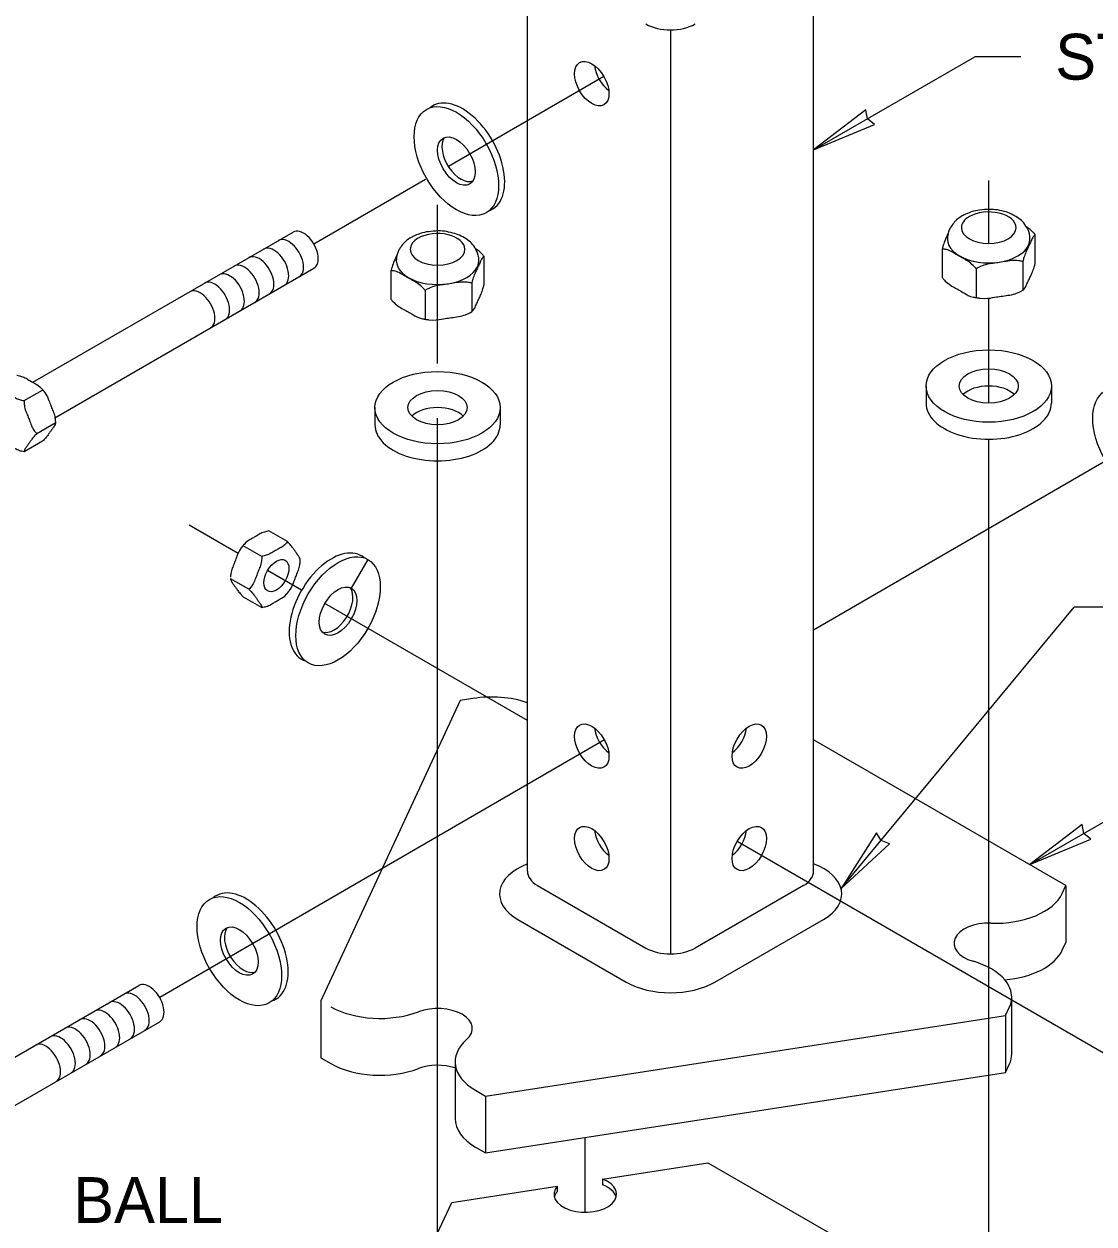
# Model space of a CAD drawing. Extents: x 99862 to 103151, y 99997 to 117076.
# Drawn here: x 100962.7 to 101336, y 103787.3 to 104205.8 of the extents above; entities that cross this region are included whole.
import ezdxf

# ---------------------------------------------------------------- set-up
doc = ezdxf.new("R2010")
doc.units = 0
for name, color, linetype in [('Level 12', 7, 'Continuous'), ('Level 13', 7, 'Continuous'), ('Level 15', 7, 'Continuous'), ('Level 20', 7, 'Continuous'), ('Level 4', 7, 'Continuous'), ('Level 6', 7, 'Continuous'), ('Level 7', 7, 'Continuous'), ('Level 8', 7, 'Continuous')]:
    doc.layers.add(name, color=color, linetype=linetype)

msp = doc.modelspace()

# ---------------------------------------------------------------- linework, layer by layer
at = {"layer": 'Level 12'}
for p, q in [((101315.52, 104122.4), (101315.52, 104132.32)), ((101283.03, 104127.29), (101283.03, 104117.38)), ((101123.26, 104114.87), (101123.26, 104124.78)), ((101311.17, 104122.94), (101311.17, 104113.02)), ((101090.76, 104119.76), (101090.76, 104109.84)), ((101294.92, 104120.42), (101294.92, 104110.51)), ((101118.91, 104115.4), (101118.91, 104105.49)), ((101102.66, 104112.89), (101102.66, 104102.98)), ((101277.42, 104079.54), (101277.42, 104073.59)), ((101321.13, 104079.54), (101321.13, 104073.59)), ((101085.16, 104072.01), (101085.16, 104066.06)), ((101128.86, 104072.01), (101128.86, 104066.06))]:
    msp.add_line(p, q, dxfattribs=at)
for centre, major_axis, start_param, end_param in [((101299.28, 104134.76), (9.54, 0), 2.356194, 3.141593), ((101299.28, 104134.76), (9.54, 0), 6.283185, 8.63938), ((101299.28, 104134.76), (9.54, 0), 3.141593, 6.283185), ((101107.01, 104127.23), (9.54, 0), 2.356194, 3.141593), ((101107.01, 104127.23), (9.54, 0), 6.283185, 8.63938), ((101299.28, 104130.79), (-14.39, 0), 0, 3.141593), ((101107.01, 104127.23), (9.54, 0), 3.141593, 6.283185), ((101107.01, 104123.26), (-14.39, 0), 0, 3.141593), ((101299.28, 104073.59), (-10.32, 0), 3.664192, 5.760586), ((101107.01, 104066.06), (-10.32, 0), 3.664192, 5.760586), ((101299.28, 104073.59), (-21.85, 0), 0, 3.141593), ((101107.01, 104066.06), (-21.85, 0), 0, 3.141593)]:
    msp.add_ellipse(centre, major_axis=major_axis, ratio=0.57735, start_param=start_param, end_param=end_param, dxfattribs=at)
for centre, major_axis in [((101299.28, 104079.54), (-21.85, 0)), ((101107.01, 104072.01), (-21.85, 0)), ((101299.28, 104079.54), (-10.32, 0)), ((101107.01, 104072.01), (-10.32, 0))]:
    msp.add_ellipse(centre, major_axis=major_axis, ratio=0.57735, dxfattribs=at)
for points, degree in [([(101313.67, 104130.79), (101313.67, 104132.32), (101313.12, 104134.07), (101311.44, 104136.67), (101310.04, 104137.95), (101307.35, 104139.55), (101305.62, 104140.23), (101302.17, 104141.06), (101299.79, 104141.24), (101295.8, 104140.97), (101293.5, 104140.45), (101291.22, 104139.49), (101290.6, 104139.18), (101288.76, 104138.12), (101287.39, 104136.94), (101286.01, 104135.02), (101285.52, 104134.08), (101285.03, 104132.5), (101284.88, 104131.57), (101284.88, 104130.79)], 3), ([(101315.52, 104132.32), (101315.27, 104132.66), (101314.96, 104132.99), (101314.03, 104133.9), (101313.29, 104134.46), (101312.54, 104134.96)], 3), ([(101121.4, 104123.26), (101121.4, 104124.79), (101120.85, 104126.54), (101119.18, 104129.14), (101117.77, 104130.41), (101115.08, 104132.02), (101113.35, 104132.7), (101109.9, 104133.52), (101107.53, 104133.71), (101103.53, 104133.43), (101101.23, 104132.91), (101098.95, 104131.95), (101098.33, 104131.65), (101096.49, 104130.58), (101095.12, 104129.41), (101093.74, 104127.49), (101093.26, 104126.55), (101092.76, 104124.97), (101092.62, 104124.04), (101092.62, 104123.26)], 3), ([(101285.15, 104132.85), (101284.56, 104131.59), (101283.88, 104130.18), (101283.23, 104128.08), (101283.12, 104127.69), (101283.03, 104127.29)], 3), ([(101315.52, 104132.32), (101315.43, 104132.31), (101315.32, 104132.22), (101314.66, 104131.52), (101313.94, 104129.89), (101313.35, 104128.61), (101312.75, 104127.33), (101312.04, 104125.88), (101311.38, 104123.73), (101311.27, 104123.33), (101311.17, 104122.94)], 3), ([(101123.26, 104124.78), (101123, 104125.13), (101122.7, 104125.46), (101121.76, 104126.37), (101121.03, 104126.93), (101120.27, 104127.43)], 3), ([(101294.92, 104120.42), (101294.66, 104120.77), (101294.36, 104121.1), (101292.55, 104122.86), (101290.6, 104123.9), (101288.97, 104124.84), (101287.35, 104125.78), (101285.4, 104126.99), (101283.59, 104127.31), (101283.29, 104127.33), (101283.03, 104127.29)], 3), ([(101092.88, 104125.31), (101092.3, 104124.06), (101091.61, 104122.64), (101090.97, 104120.55), (101090.86, 104120.16), (101090.76, 104119.76)], 3), ([(101123.26, 104124.78), (101123.16, 104124.77), (101123.05, 104124.69), (101122.39, 104123.98), (101121.68, 104122.36), (101121.08, 104121.08), (101120.49, 104119.8), (101119.77, 104118.35), (101119.11, 104116.2), (101119, 104115.8), (101118.91, 104115.4)], 3), ([(101311.17, 104122.94), (101310.82, 104123.08), (101310.4, 104123.17), (101307.93, 104123.5), (101305.27, 104123.01), (101303.05, 104122.66), (101300.83, 104122.32), (101298.16, 104121.99), (101295.69, 104120.89), (101295.28, 104120.67), (101294.92, 104120.42)], 3), ([(101311.3, 104113.07), (101311.36, 104113.11), (101311.42, 104113.16), (101312.04, 104113.83), (101312.75, 104115.45), (101313.35, 104116.73), (101313.94, 104118.01), (101314.66, 104119.46), (101315.32, 104121.61), (101315.43, 104122.01), (101315.52, 104122.4)], 3), ([(101102.66, 104112.89), (101102.4, 104113.23), (101102.09, 104113.57), (101100.28, 104115.33), (101098.33, 104116.37), (101096.71, 104117.31), (101095.08, 104118.25), (101093.14, 104119.46), (101091.33, 104119.78), (101091.02, 104119.8), (101090.76, 104119.76)], 3), ([(101118.91, 104115.4), (101118.55, 104115.54), (101118.14, 104115.63), (101115.66, 104115.97), (101113, 104115.48), (101110.78, 104115.13), (101108.56, 104114.79), (101105.9, 104114.46), (101103.43, 104113.36), (101103.01, 104113.14), (101102.66, 104112.89)], 3), ([(101119.03, 104105.54), (101119.09, 104105.58), (101119.15, 104105.63), (101119.77, 104106.29), (101120.49, 104107.91), (101121.08, 104109.2), (101121.68, 104110.48), (101122.39, 104111.93), (101123.05, 104114.08), (101123.16, 104114.47), (101123.26, 104114.87)], 3), ([(101283.03, 104117.38), (101283.29, 104117.03), (101283.59, 104116.7), (101285.4, 104114.94), (101287.35, 104113.9), (101288.97, 104112.96), (101290.57, 104112.04), (101292.47, 104110.86), (101293.99, 104110.55)], 3), ([(101090.76, 104109.84), (101091.02, 104109.5), (101091.33, 104109.17), (101093.14, 104107.4), (101095.08, 104106.36), (101096.71, 104105.43), (101098.3, 104104.51), (101100.2, 104103.33), (101101.72, 104103.02)], 3), ([(101293.99, 104110.57), (101294.75, 104110.42), (101295.52, 104110.29), (101296.27, 104110.21)], 2), ([(101296.26, 104110.2), (101298.33, 104109.97), (101300.89, 104110.45), (101303.05, 104110.78), (101305.27, 104111.12), (101307.93, 104111.45), (101310.2, 104112.47), (101310.39, 104112.56), (101310.57, 104112.66)], 3), ([(101310.57, 104112.65), (101310.79, 104112.77), (101311, 104112.89), (101311.24, 104113.03), (101311.27, 104113.05), (101311.3, 104113.07)], 3), ([(101104, 104102.67), (101106.06, 104102.44), (101108.63, 104102.92), (101110.78, 104103.25), (101113, 104103.59), (101115.66, 104103.92), (101117.94, 104104.93), (101118.12, 104105.02), (101118.31, 104105.12)], 3), ([(101118.3, 104105.12), (101118.52, 104105.24), (101118.74, 104105.36), (101118.97, 104105.5), (101119, 104105.52), (101119.03, 104105.54)], 3), ([(101101.73, 104103.04), (101102.49, 104102.88), (101103.25, 104102.76), (101104.01, 104102.67)], 2)]:
    msp.add_open_spline(points, degree=degree, dxfattribs=at)
at = {"layer": 'Level 13'}
for p, q in [((100965.84, 104080.85), (101056.59, 104133.25)), ((100973.53, 104068.47), (101063.9, 104120.65)), ((100962.77, 104074.45), (100969.21, 104078.16)), ((100967.23, 104062.95), (100973.67, 104066.67)), ((100969.21, 104060.32), (100962.77, 104056.6)), ((101054.61, 104025.29), (101048.17, 104029.01)), ((101045.69, 104020.14), (101039.25, 104023.86)), ((101082.71, 104019.05), (101076.93, 104009.02)), ((101041.22, 104008.65), (101034.79, 104012.36)), ((101039.25, 104006.02), (101045.69, 104002.3)), ((100912.03, 103818.04), (101002.8, 103870.45)), ((100919.72, 103805.66), (101010.09, 103857.84))]:
    msp.add_line(p, q, dxfattribs=at)
for centre, major_axis in [((101113.57, 104158.01), (-10.41, 18.04)), ((101113.57, 104158.01), (-4.63, 8.02)), ((101350.3, 104059.81), (10.41, -18.04)), ((101072.3, 104001.01), (-10.41, -18.04)), ((101050.79, 104013.43), (-3.09, -5.34)), ((101072.3, 104001.01), (-4.63, -8.02)), ((101037.86, 103882.44), (10.41, -18.04)), ((101037.86, 103882.44), (4.63, -8.02))]:
    msp.add_ellipse(centre, major_axis=major_axis, ratio=0.57735, dxfattribs=at)
for centre, major_axis, start_param, end_param in [((101115.71, 104159.23), (-10.41, 18.04), 3.035348, 6.38194), ((101115.09, 104159.32), (-4.63, 8.02), 0.295844, 3.063613), ((101055.1, 104123.98), (3.64, -6.31), 6.283185, 9.424783), ((101060.25, 104126.95), (3.64, -6.31), 6.283179, 9.429517), ((101049.95, 104121), (3.64, -6.31), 6.283185, 9.424778), ((101039.64, 104115.05), (3.64, -6.31), 6.283185, 9.424784), ((101044.79, 104118.03), (3.64, -6.31), 6.283185, 9.424778), ((101034.49, 104112.08), (3.64, -6.31), 6.283185, 9.42478), ((101024.18, 104106.13), (3.64, -6.31), 6.283185, 9.424778), ((101029.33, 104109.1), (3.64, -6.31), 6.283185, 9.424778), ((101069.98, 104002.29), (-10.41, -18.04), 3.042453, 6.404476), ((101070.95, 104002.04), (-4.63, -8.02), 0.083455, 2.907882), ((101040.18, 103883.72), (10.41, -18.04), 6.161895, 9.523918), ((101039.21, 103883.48), (4.63, -8.02), 3.375303, 6.19973), ((101006.44, 103864.14), (-3.64, 6.31), 3.141586, 6.283198), ((101001.29, 103861.17), (-3.64, 6.31), 3.141588, 6.283197), ((100990.98, 103855.22), (-3.64, 6.31), 3.141587, 6.283191), ((100996.14, 103858.19), (-3.64, 6.31), 3.141585, 6.283198), ((100985.83, 103852.24), (-3.64, 6.31), 3.141589, 6.283194), ((100980.68, 103849.27), (-3.64, 6.31), 3.141586, 6.283196), ((100970.37, 103843.32), (-3.64, 6.31), 3.14159, 6.283193), ((100975.52, 103846.29), (-3.64, 6.31), 3.141587, 6.283194)]:
    msp.add_ellipse(centre, major_axis=major_axis, ratio=0.57735, start_param=start_param, end_param=end_param, dxfattribs=at)
for points, degree in [([(100960.29, 104083.31), (100960.61, 104083.27), (100960.94, 104083.2), (100962.77, 104082.69), (100964.17, 104081.81), (100965.39, 104081.11), (100966.59, 104080.41), (100968.08, 104079.62), (100968.85, 104078.74)], 3), ([(100953.85, 104079.6), (100953.92, 104079.41), (100954.05, 104079.22), (100954.94, 104078.17), (100956.45, 104077.35), (100957.67, 104076.65), (100958.89, 104075.95), (100960.3, 104075.07), (100962.12, 104074.56), (100962.45, 104074.48), (100962.77, 104074.45)], 3), ([(100968.85, 104078.74), (100969.22, 104078.31), (100969.58, 104077.86), (100969.91, 104077.41)], 2), ([(100969.91, 104077.41), (100970.84, 104076.15), (100971.49, 104074.31), (100972.08, 104072.78), (100972.69, 104071.21), (100973.48, 104069.36), (100973.67, 104067.5), (100973.68, 104067.35), (100973.69, 104067.19)], 3), ([(100962.77, 104074.45), (100962.74, 104074.12), (100962.76, 104073.77), (100962.97, 104071.75), (100963.75, 104069.9), (100964.36, 104068.33), (100964.97, 104066.76), (100965.65, 104064.84), (100966.8, 104063.36), (100967.01, 104063.13), (100967.23, 104062.95)], 3), ([(100973.69, 104066.57), (100973.69, 104066.51), (100973.68, 104066.45), (100973.48, 104065.8), (100972.69, 104064.73), (100972.08, 104063.86), (100971.47, 104063), (100970.8, 104061.99), (100969.65, 104060.75), (100969.44, 104060.53), (100969.21, 104060.32)], 3), ([(100973.69, 104067.19), (100973.69, 104067.01), (100973.69, 104066.82), (100973.69, 104066.62), (100973.69, 104066.59), (100973.69, 104066.57)], 3), ([(100962.77, 104056.6), (100962.45, 104056.64), (100962.12, 104056.72), (100960.3, 104057.23), (100958.89, 104058.11), (100957.67, 104058.81), (100956.47, 104059.5), (100954.98, 104060.3), (100954.22, 104061.18)], 3), ([(100967.23, 104062.95), (100967.01, 104062.74), (100966.8, 104062.52), (100965.65, 104061.28), (100964.97, 104060.27), (100964.36, 104059.41), (100963.75, 104058.54), (100962.97, 104057.47), (100962.76, 104056.77), (100962.74, 104056.67), (100962.77, 104056.6)], 3), ([(101048.17, 104029.01), (101047.85, 104028.97), (101047.52, 104028.9), (101045.69, 104028.38), (101044.29, 104027.51), (101043.07, 104026.81), (101041.87, 104026.11), (101040.38, 104025.31), (101039.61, 104024.44)], 3), ([(101038.55, 104023.1), (101037.62, 104021.85), (101036.97, 104020), (101036.38, 104018.48), (101035.77, 104016.91), (101034.98, 104015.06), (101034.79, 104013.2), (101034.78, 104013.05), (101034.77, 104012.89)], 3), ([(101039.61, 104024.44), (101039.24, 104024.01), (101038.88, 104023.56), (101038.55, 104023.1)], 2), ([(101054.61, 104025.29), (101054.54, 104025.11), (101054.41, 104024.92), (101053.52, 104023.86), (101052, 104023.05), (101050.79, 104022.35), (101049.57, 104021.65), (101048.16, 104020.77), (101046.34, 104020.26), (101046.01, 104020.18), (101045.69, 104020.14)], 3), ([(101059.08, 104019.05), (101059.08, 104019.1), (101059.07, 104019.16), (101058.87, 104019.81), (101058.09, 104020.88), (101057.48, 104021.75), (101056.87, 104022.62), (101056.19, 104023.63), (101055.05, 104024.86), (101054.83, 104025.08), (101054.61, 104025.29)], 3), ([(101045.69, 104020.14), (101045.71, 104019.82), (101045.7, 104019.47), (101045.49, 104017.45), (101044.7, 104015.6), (101044.1, 104014.03), (101043.49, 104012.45), (101042.81, 104010.54), (101041.66, 104009.06), (101041.45, 104008.82), (101041.22, 104008.65)], 3), ([(101055.31, 104008.21), (101056.23, 104009.46), (101056.89, 104011.31), (101057.48, 104012.83), (101058.09, 104014.4), (101058.87, 104016.25), (101059.07, 104018.11), (101059.08, 104018.26), (101059.08, 104018.42)], 3), ([(101059.08, 104018.42), (101059.09, 104018.61), (101059.09, 104018.79), (101059.08, 104018.99), (101059.08, 104019.02), (101059.08, 104019.05)], 3), ([(101034.77, 104012.26), (101034.77, 104012.21), (101034.78, 104012.15), (101034.98, 104011.5), (101035.77, 104010.43), (101036.38, 104009.56), (101036.99, 104008.69), (101037.66, 104007.69), (101038.81, 104006.45), (101039.02, 104006.23), (101039.25, 104006.02)], 3), ([(101041.22, 104008.65), (101041.45, 104008.44), (101041.66, 104008.21), (101042.81, 104006.98), (101043.49, 104005.97), (101044.1, 104005.1), (101044.7, 104004.24), (101045.49, 104003.17), (101045.7, 104002.47), (101045.71, 104002.37), (101045.69, 104002.3)], 3), ([(101045.69, 104002.3), (101046.01, 104002.34), (101046.34, 104002.41), (101048.16, 104002.93), (101049.57, 104003.8), (101050.79, 104004.51), (101051.99, 104005.2), (101053.48, 104006), (101054.24, 104006.88)], 3), ([(101054.24, 104006.88), (101054.62, 104007.31), (101054.98, 104007.76), (101055.31, 104008.21)], 2)]:
    msp.add_open_spline(points, degree=degree, dxfattribs=at)
at = {"layer": 'Level 15'}
for p, q in [((101238.18, 104161.91), (101294.48, 104194.41)), ((101310.48, 104194.41), (101294.48, 104194.41)), ((101165.05, 104187.46), (101110.77, 104156.13)), ((101102.86, 104151.56), (101063.89, 104129.07)), ((101299.28, 104129.25), (101299.28, 104151.29)), ((101107.01, 104087.36), (101107.01, 104142.8)), ((101299.28, 104073.58), (101299.28, 104110.24)), ((101107.01, 104031.69), (101107.01, 104068.35)), ((101354.82, 104062), (101238.18, 103994.42)), ((101299.28, 103710.11), (101299.28, 104060.98)), ((101037.44, 104021.13), (101020.33, 104031.01)), ((101107.01, 103435.1), (101107.01, 104031.69)), ((101059.59, 104008.34), (101047.7, 104015.21)), ((101138.36, 103962.9), (101067.73, 104003.68)), ((101247.75, 103904.29), (101329.08, 104002.46)), ((101345.08, 104002.46), (101329.08, 104002.46)), ((101165.2, 103956.13), (101010.09, 103866.25)), ((101313.59, 103912.62), (101369.88, 103945.12)), ((101382.18, 103822.14), (101211.49, 103920.68)), ((101158.53, 103791.37), (101158.53, 103817.47))]:
    msp.add_line(p, q, dxfattribs=at)
for points in [[(101238.18, 104161.91), (101259.45, 104170.74), (101257.04, 104172.8), (101256.46, 104175.91)], [(101313.59, 103912.62), (101334.85, 103921.45), (101332.44, 103923.51), (101331.87, 103926.62)], [(101247.75, 103904.29), (101264.66, 103919.91), (101261.7, 103921.01), (101260.08, 103923.73)]]:
    msp.add_lwpolyline(points, close=True, dxfattribs=at)
at = {"layer": 'Level 4'}
for p, q in [((101138.36, 103910.3), (101138.36, 104232.59)), ((101238.18, 103910.3), (101238.18, 104232.59)), ((101188.27, 104203.77), (101188.27, 103881.48))]:
    msp.add_line(p, q, dxfattribs=at)
for centre, major_axis, start_param, end_param in [((101188.27, 104210.78), (-12.14, 0), 0.785398, 2.356194), ((101167.67, 104188.97), (4.25, -7.36), 4.082549, 5.342229), ((101167.67, 103957.91), (4.25, -7.36), 4.082549, 5.342229), ((101208.87, 103957.91), (-4.25, -7.36), 0.940957, 2.200636), ((101167.67, 103922.19), (4.25, -7.36), 4.082549, 5.342229), ((101208.87, 103922.19), (-4.25, -7.36), 0.940957, 2.200636)]:
    msp.add_ellipse(centre, major_axis=major_axis, ratio=0.57735, start_param=start_param, end_param=end_param, dxfattribs=at)
for centre, major_axis in [((101160.8, 104185.01), (4.25, -7.36)), ((101160.8, 103953.95), (4.25, -7.36)), ((101215.74, 103953.95), (-4.25, -7.36)), ((101160.8, 103918.23), (4.25, -7.36)), ((101215.74, 103918.23), (-4.25, -7.36))]:
    msp.add_ellipse(centre, major_axis=major_axis, ratio=0.57735, dxfattribs=at)
at = {"layer": 'Level 6'}
for p, q in [((101114.85, 103969.86), (101066.24, 103865.12)), ((101119.96, 103970.65), (101114.85, 103969.86)), ((101326.22, 103905.33), (101238.18, 103956.16)), ((101324.93, 103902.55), (101326.22, 103905.33)), ((101326.22, 103905.33), (101326.22, 103885.51)), ((101324.93, 103882.73), (101326.22, 103885.51)), ((101307.28, 103846.56), (101307.28, 103866.38)), ((101066.24, 103865.12), (101066.24, 103845.29)), ((101305.17, 103859.98), (101306.45, 103862.75)), ((101123.75, 103831.91), (101305.17, 103859.98)), ((101305.17, 103859.98), (101305.17, 103840.15)), ((101066.24, 103845.29), (101069.76, 103843.26)), ((101113.12, 103843.86), (101113.12, 103824.03)), ((101305.17, 103840.15), (101306.45, 103842.93)), ((101123.75, 103812.09), (101305.17, 103840.15)), ((101120.23, 103833.95), (101123.75, 103831.91)), ((101123.75, 103831.91), (101123.75, 103812.09)), ((101120.23, 103814.12), (101123.75, 103812.09))]:
    msp.add_line(p, q, dxfattribs=at)
for centre, major_axis, start_param, end_param in [((101125.94, 103957.06), (-24.28, 0), 4.175574, 4.987015), ((101301.47, 103906.18), (-24.28, 0), 1.510356, 2.879794), ((101299.28, 103885.19), (-12.14, 0), 4.652112, 7.390662), ((101283, 103866.38), (-24.28, 0), 3.591411, 4.249233), ((101301.47, 103886.36), (-24.28, 0), 1.711023, 2.879794), ((101283, 103866.38), (-24.28, 0), 3.141593, 3.591411), ((101283, 103866.38), (-24.28, 0), 2.879794, 3.141593), ((101086.93, 103872.99), (-24.28, 0), 0.785398, 2.154673), ((101107.01, 103855.45), (-12.14, 0), 2.557552, 5.296429), ((101137.4, 103843.86), (-24.28, 0), 5.699308, 7.068583), ((101283, 103846.56), (-24.28, 0), 2.879794, 3.141593), ((101086.93, 103853.17), (-24.28, 0), 0.785398, 2.154673), ((101107.01, 103835.63), (-12.14, 0), 4.185432, 5.296429), ((101137.4, 103824.03), (-24.28, 0), 0, 0.785398)]:
    msp.add_ellipse(centre, major_axis=major_axis, ratio=0.57735, start_param=start_param, end_param=end_param, dxfattribs=at)
at = {"layer": 'Level 7'}
for p, q in [((101141.92, 103905.34), (101179.69, 103883.53)), ((101234.63, 103905.34), (101196.86, 103883.53)), ((101135.05, 103893.45), (101172.82, 103871.64)), ((101203.72, 103871.64), (101241.59, 103893.5))]:
    msp.add_line(p, q, dxfattribs=at)
for centre, major_axis, start_param, end_param in [((101150.5, 103902.37), (-21.85, 0), 5.30142, 7.068583), ((101226.14, 103902.42), (-21.85, 0), 2.356194, 4.128615), ((101150.5, 103910.3), (-12.14, 0), 0, 0.785398), ((101226.04, 103910.3), (-12.14, 0), 2.356194, 3.141593), ((101188.27, 103888.49), (-12.14, 0), 0.785398, 2.356194), ((101188.27, 103880.56), (-21.85, 0), 0.785398, 2.356194)]:
    msp.add_ellipse(centre, major_axis=major_axis, ratio=0.57735, start_param=start_param, end_param=end_param, dxfattribs=at)
at = {"layer": 'Level 8'}
for p, q in [((101164.51, 103802.96), (101201.34, 103808.66)), ((101201.34, 103808.66), (101318.29, 103741.14)), ((101111.95, 103794.83), (101148.78, 103800.53)), ((101148.78, 103800.53), (101148.78, 103798.54)), ((101164.51, 103802.96), (101164.51, 103800.98)), ((101069.14, 103702.59), (101111.95, 103794.83))]:
    msp.add_line(p, q, dxfattribs=at)
for centre, start_param, end_param in [((101158.53, 103797.68), 5.815222, 10.416341), ((101158.53, 103795.7), 3.299381, 4.133156), ((101158.53, 103795.7), 5.815222, 6.125397)]:
    msp.add_ellipse(centre, major_axis=(-10.93, 0), ratio=0.57735, start_param=start_param, end_param=end_param, dxfattribs=at)

# ---------------------------------------------------------------- texts
at = {"layer": 'Level 20'}
for s, p in [('STEEL TUBING', (101322.47, 104186.41)), ('BALL', (100979.89, 103787.62))]:
    msp.add_text(s, height=16, dxfattribs=at).set_placement(p)

doc.saveas('drawing.dxf')
